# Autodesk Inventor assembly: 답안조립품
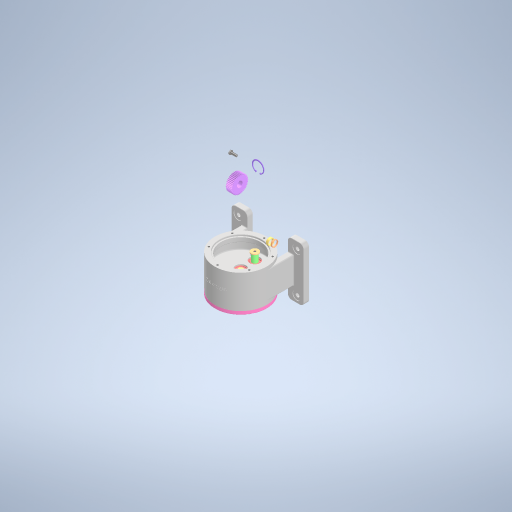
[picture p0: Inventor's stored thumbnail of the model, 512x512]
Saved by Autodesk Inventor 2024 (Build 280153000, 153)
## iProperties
Created: 2025-12
Part Number: 답안조립품
Document SubType Name: Assembly
Designer: Edu07
Author: Edu07
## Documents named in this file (17)
- C:\Users\Edu07\OneDrive\Desktop\751203V1004\답안조립품.iam
- C:\Users\Edu07\OneDrive\Desktop\751203V1004\6각 구멍붙이 볼트 M4x10\6각 구멍붙이 볼트 M4x10.ipt
- C:\Users\Edu07\OneDrive\Desktop\751203V1004\6각 머리 볼트 M8x20\6각 머리 볼트 M8x20.ipt
- C:\Users\Edu07\OneDrive\Desktop\751203V1004\C형 멈춤링 구멍용 42\C형 멈춤링 구멍용 42.ipt
- C:\Users\Edu07\OneDrive\Desktop\751203V1004\구동 기어\구동 기어.ipt
- C:\Users\Edu07\OneDrive\Desktop\751203V1004\기어 축\기어 축.ipt
- C:\Users\Edu07\OneDrive\Desktop\751203V1004\깊은 홈 볼 베어링 6004\깊은 홈 볼 베어링 6004.ipt
- C:\Users\Edu07\OneDrive\Desktop\751203V1004\깊은 홈 볼 베어링 6005\깊은 홈 볼 베어링 6005.ipt
- C:\Users\Edu07\OneDrive\Desktop\751203V1004\본체.ipt
- C:\Users\Edu07\OneDrive\Desktop\751203V1004\엔드 캡\엔드 캡.ipt
- C:\Users\Edu07\OneDrive\Desktop\751203V1004\오일 실 25 40 8\오일 실 25 40 8.ipt
- C:\Users\Edu07\OneDrive\Desktop\751203V1004\종동 기어\종동 기어.ipt
- C:\Users\Edu07\OneDrive\Desktop\751203V1004\출력 축\출력 축.ipt
- C:\Users\Edu07\OneDrive\Desktop\751203V1004\칼라 1\칼라 1.ipt
- C:\Users\Edu07\OneDrive\Desktop\751203V1004\칼라 2\칼라 2.ipt
- C:\Users\Edu07\OneDrive\Desktop\751203V1004\커버\커버.ipt
- C:\Users\Edu07\OneDrive\Desktop\751203V1004\평행 키 6x6x16\평행 키 6x6x16.ipt
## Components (13 placed, 4 different names)
1. 6각 구멍붙이 볼트 M4x10:1
2. C형 멈춤링 구멍용 42:1
3. 구동 기어:1
4. 6각 머리 볼트 M8x20:2
5. 6각 구멍붙이 볼트 M4x10:2
6. 6각 머리 볼트 M8x20:3
7. 6각 머리 볼트 M8x20:4
8. 6각 머리 볼트 M8x20:5
9. 6각 머리 볼트 M8x20:6
10. 6각 머리 볼트 M8x20:7
11. 6각 머리 볼트 M8x20:8
12. 6각 머리 볼트 M8x20:9
13. 6각 머리 볼트 M8x20:10
